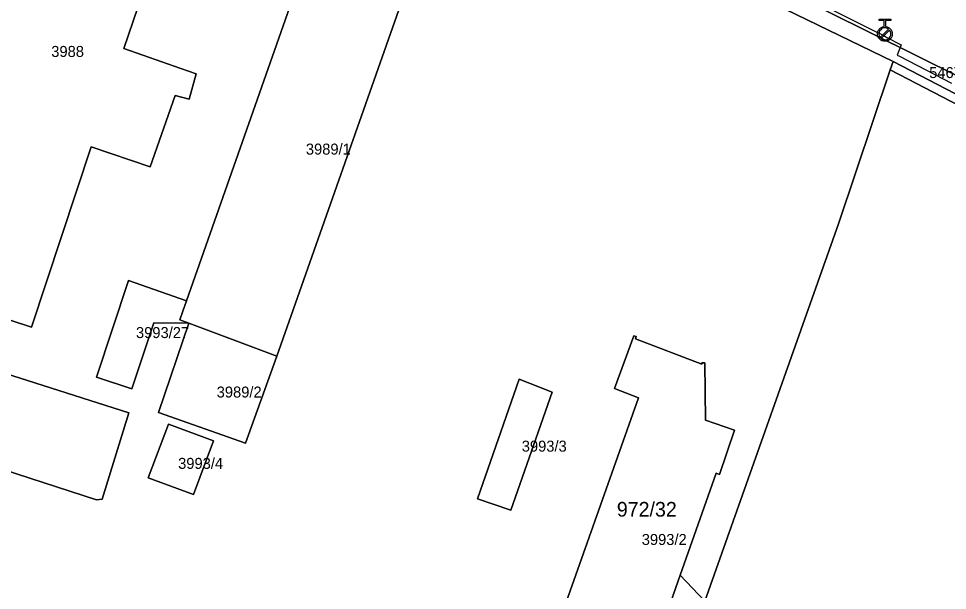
# Model space of a CAD drawing. Extents: x -570104 to -569328, y -1087857 to -1087418.
# Drawn here: x -569658.3 to -569531.5, y -1087753.5 to -1087675.5 of the extents above; entities that cross this region are included whole.
import ezdxf

# ---------------------------------------------------------------- set-up
doc = ezdxf.new("R2010")
doc.units = 0
for name, color, linetype in [('Adresní místo-text', 7, 'Continuous'), ('Default', 7, 'Continuous'), ('Hydrant', 7, 'Continuous'), ('Parcela-polygon', 7, 'Continuous'), ('Parcela-text', 7, 'Continuous'), ('Vodovodní řad', 7, 'Continuous')]:
    doc.layers.add(name, color=color, linetype=linetype)

msp = doc.modelspace()

# ---------------------------------------------------------------- linework, layer by layer
at = {"layer": 'Default'}
for points in [[(-569539.97, -1087676.62), (-569539.62, -1087676.65), (-569539.36, -1087676.91), (-569539.07, -1087677.21), (-569539.07, -1087677.62), (-569539.07, -1087678.04), (-569539.36, -1087678.33), (-569539.66, -1087678.62), (-569540.07, -1087678.62), (-569540.49, -1087678.62), (-569540.78, -1087678.33), (-569541.07, -1087678.03), (-569541.07, -1087677.62), (-569541.07, -1087677.2), (-569540.78, -1087676.91), (-569540.52, -1087676.65), (-569540.16, -1087676.62)], [(-569539.56, -1087676.98), (-569539.78, -1087676.81), (-569540.07, -1087676.81), (-569540.41, -1087676.8), (-569540.65, -1087677.04), (-569540.88, -1087677.28), (-569540.88, -1087677.62), (-569540.89, -1087677.91), (-569540.71, -1087678.12)], [(-569540.58, -1087678.26), (-569540.36, -1087678.43), (-569540.07, -1087678.43), (-569539.74, -1087678.43), (-569539.5, -1087678.19), (-569539.26, -1087677.96), (-569539.26, -1087677.62), (-569539.26, -1087677.33), (-569539.43, -1087677.12)]]:
    msp.add_open_spline(points, degree=3, dxfattribs=at)
at = {"layer": 'Hydrant'}
for points in [[(-569540.16, -1087676.62), (-569540.16, -1087675.81), (-569540.85, -1087675.81), (-569540.85, -1087675.62), (-569539.28, -1087675.62), (-569539.28, -1087675.81), (-569539.97, -1087675.81), (-569539.97, -1087676.62)], [(-569540.71, -1087678.12), (-569539.56, -1087676.98)], [(-569539.43, -1087677.12), (-569540.58, -1087678.26)]]:
    msp.add_lwpolyline(points, dxfattribs=at)
at = {"layer": 'Parcela-polygon'}
for points in [[(-569668.31, -1087613.41), (-569657.69, -1087618.95), (-569643.42, -1087626.13), (-569631.73, -1087631.98), (-569610.29, -1087642.72), (-569597.52, -1087649.08), (-569596.28, -1087649.69), (-569583.46, -1087656.2), (-569547.98, -1087674.52), (-569517.48, -1087689.67)], [(-569674.15, -1087711.83), (-569651.41, -1087642.32), (-569633.25, -1087648.27), (-569643.94, -1087679.59), (-569636.12, -1087682.33), (-569634.05, -1087683.06), (-569635, -1087686.54), (-569636.91, -1087686.03), (-569640.33, -1087695.74), (-569648.38, -1087693.02), (-569656.5, -1087717.61), (-569674.15, -1087711.83)], [(-569635.37, -1087714.02), (-569616.89, -1087661.48), (-569616.35, -1087659.96), (-569615.13, -1087660.4), (-569603.05, -1087664.75), (-569623.04, -1087721.56), (-569627.3, -1087733.45), (-569639.21, -1087729.26), (-569635.07, -1087717.06), (-569639.81, -1087717), (-569642.81, -1087726.03), (-569647.65, -1087724.43), (-569643.27, -1087711.24), (-569635.37, -1087714.02)], [(-569584.06, -1087756.52), (-569573.68, -1087727.24), (-569576.95, -1087725.98), (-569574.35, -1087718.78), (-569573.99, -1087718.9), (-569574.1, -1087719.21), (-569565.06, -1087722.67), (-569565.06, -1087722.48), (-569564.66, -1087722.48), (-569564.53, -1087730.3), (-569560.6, -1087731.68), (-569562.64, -1087737.69), (-569563.11, -1087737.53), (-569567.99, -1087751.44), (-569564.62, -1087755), (-569546.41, -1087703.53), (-569539.35, -1087682.53), (-569538.96, -1087681.38), (-569578.63, -1087662.1)], [(-569577.45, -1087857.02), (-569556.58, -1087797.77), (-569556.02, -1087796.19), (-569541.61, -1087801.32), (-569541.34, -1087800.75), (-569529.77, -1087805.11), (-569529.88, -1087805.5), (-569510.5, -1087812.41), (-569480.79, -1087729.63), (-569489.42, -1087709.06), (-569489.76, -1087708.24), (-569539.35, -1087682.53), (-569546.41, -1087703.53), (-569564.62, -1087755), (-569575.22, -1087784.93), (-569579.43, -1087783.46), (-569581.07, -1087788.14), (-569602.51, -1087849.39), (-569605.18, -1087857.02)], [(-569704.22, -1087722.8), (-569700.58, -1087711.04), (-569643.25, -1087729.31), (-569646.89, -1087741.06), (-569647.63, -1087741.14), (-569704.22, -1087722.8)], [(-569585.46, -1087726.47), (-569591.11, -1087742.58), (-569595.68, -1087741.01), (-569589.98, -1087724.71), (-569585.46, -1087726.47)], [(-569640.6, -1087738.17), (-569637.83, -1087730.82), (-569631.69, -1087733.11), (-569634.41, -1087740.42), (-569640.6, -1087738.17)]]:
    msp.add_lwpolyline(points, dxfattribs=at)
for points in [[(-569674.15, -1087711.83), (-569656.5, -1087717.61), (-569648.38, -1087693.02), (-569640.33, -1087695.74), (-569636.91, -1087686.03), (-569635, -1087686.54), (-569634.05, -1087683.06), (-569636.12, -1087682.33), (-569643.94, -1087679.59), (-569633.25, -1087648.27), (-569651.41, -1087642.32)], [(-569538.96, -1087681.38), (-569481.19, -1087711.33), (-569480.67, -1087711.59), (-569481.46, -1087710.69), (-569482.62, -1087709.76), (-569487.65, -1087706.59), (-569517.48, -1087689.67), (-569547.98, -1087674.52), (-569583.46, -1087656.2), (-569581.88, -1087657.43), (-569580.22, -1087659.19), (-569578.84, -1087661.42), (-569578.63, -1087662.1)], [(-569635.07, -1087717.06), (-569623.04, -1087721.56), (-569603.05, -1087664.75), (-569615.13, -1087660.4), (-569616.35, -1087659.96), (-569616.89, -1087661.48), (-569635.37, -1087714.02), (-569635.87, -1087715.43), (-569636.29, -1087716.6)], [(-569480.2, -1087727.99), (-569478.82, -1087724.15), (-569479.55, -1087722.98), (-569479.11, -1087718.52), (-569479.11, -1087715.5), (-569479.61, -1087713.5), (-569480.67, -1087711.59), (-569481.19, -1087711.33), (-569538.96, -1087681.38), (-569539.35, -1087682.53), (-569489.76, -1087708.24), (-569489.42, -1087709.06), (-569484.19, -1087712.45), (-569482.77, -1087713.8), (-569482.16, -1087715.26), (-569482.07, -1087716.83), (-569482.23, -1087719.78), (-569482.55, -1087722.4), (-569482.46, -1087723.59), (-569482.05, -1087724.68)], [(-569704.22, -1087722.8), (-569647.63, -1087741.14), (-569646.89, -1087741.06), (-569643.25, -1087729.31), (-569700.58, -1087711.04)], [(-569635.87, -1087715.43), (-569635.37, -1087714.02), (-569643.27, -1087711.24), (-569647.65, -1087724.43), (-569642.81, -1087726.03), (-569639.81, -1087717), (-569635.07, -1087717.06), (-569636.29, -1087716.6)], [(-569627.3, -1087733.45), (-569623.04, -1087721.56), (-569635.07, -1087717.06), (-569639.21, -1087729.26)], [(-569584.06, -1087756.52), (-569578.91, -1087758.34), (-569580, -1087761.41), (-569582.54, -1087768.59), (-569575.3, -1087771.06), (-569572.74, -1087764.06), (-569571.59, -1087760.9), (-569570.89, -1087761.14), (-569570.64, -1087760.43), (-569571.11, -1087760.27), (-569567.99, -1087751.44), (-569563.11, -1087737.53), (-569562.64, -1087737.69), (-569560.6, -1087731.68), (-569564.53, -1087730.3), (-569564.66, -1087722.48), (-569565.06, -1087722.48), (-569565.06, -1087722.67), (-569574.1, -1087719.21), (-569573.99, -1087718.9), (-569574.35, -1087718.78), (-569576.95, -1087725.98), (-569573.68, -1087727.24)], [(-569585.46, -1087726.47), (-569589.98, -1087724.71), (-569595.68, -1087741.01), (-569591.11, -1087742.58)], [(-569640.6, -1087738.17), (-569634.41, -1087740.42), (-569631.69, -1087733.11), (-569637.83, -1087730.82)], [(-569578.99, -1087782.13), (-569585.86, -1087779.89), (-569587.15, -1087783.68), (-569581.07, -1087788.14), (-569579.43, -1087783.46), (-569575.22, -1087784.93), (-569564.62, -1087755), (-569567.99, -1087751.44), (-569571.11, -1087760.27), (-569570.64, -1087760.43), (-569570.89, -1087761.14), (-569571.59, -1087760.9), (-569572.74, -1087764.06), (-569575.3, -1087771.06)]]:
    msp.add_lwpolyline(points, close=True, dxfattribs=at)
at = {"layer": 'Vodovodní řad'}
for points in [[(-569704.52, -1087621.35), (-569688.87, -1087604.08), (-569665.83, -1087615.89), (-569665.36, -1087616.11), (-569633.42, -1087631.08), (-569632.62, -1087631.48), (-569601.79, -1087646.96), (-569583.18, -1087656.3), (-569555.45, -1087670.22), (-569542.09, -1087676.92), (-569540.21, -1087677.85)], [(-569540.21, -1087677.85), (-569539.82, -1087678.09), (-569537.83, -1087679.12), (-569538.4, -1087680.5), (-569538.29, -1087680.55), (-569538.18, -1087680.6), (-569535.61, -1087681.94), (-569530.97, -1087684.32)]]:
    msp.add_lwpolyline(points, dxfattribs=at)

# ---------------------------------------------------------------- texts
at = {"layer": 'Adresní místo-text'}
msp.add_text('972/32', height=2, dxfattribs=at).set_placement((-569576.65, -1087743.45))
at = {"layer": 'Parcela-text'}
for s, p in [('3988', (-569653.82, -1087680.76)), ('5467/42', (-569534.03, -1087683.64)), ('3989/1', (-569619.08, -1087694.08)), ('3993/27', (-569642.26, -1087719.1)), ('3989/2', (-569631.25, -1087727.21)), ('3993/3', (-569589.62, -1087734.59)), ('3993/4', (-569636.51, -1087736.94)), ('3993/2', (-569573.25, -1087747.32))]:
    msp.add_text(s, height=1.5, dxfattribs=at).set_placement(p)

doc.saveas('drawing.dxf')
